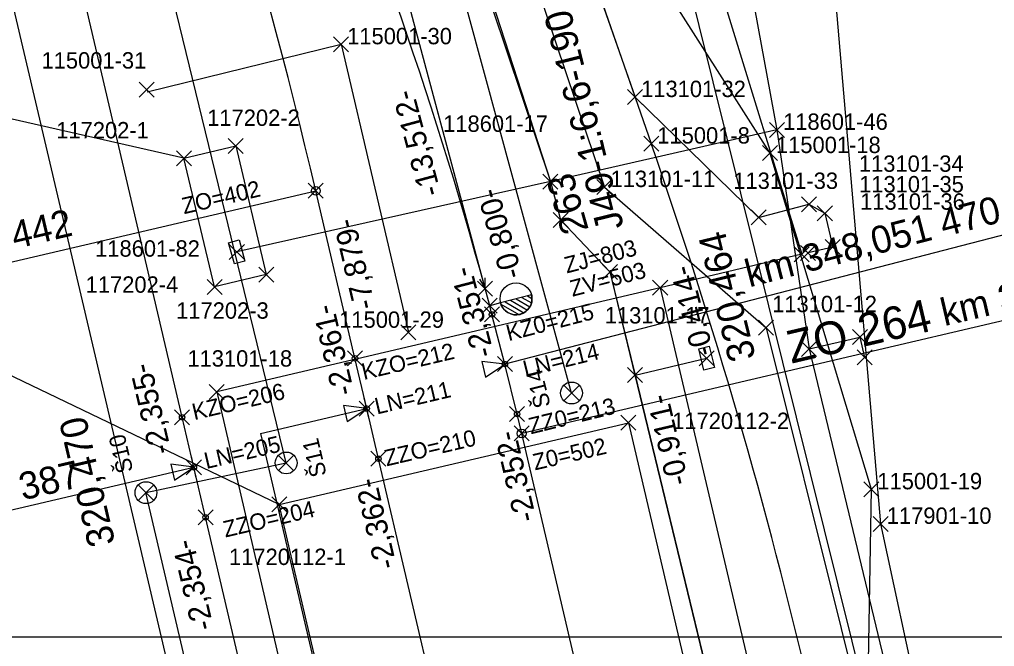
# Model space of a CAD drawing. Extents: x -821029 to -820632, y -1070881 to -1069931.
# Drawn here: x -820817.11 to -820772.47, y -1070448.01 to -1070419.3 of the extents above; entities that cross this region are included whole.
import ezdxf

# ---------------------------------------------------------------- set-up
doc = ezdxf.new("R2010")
doc.units = 0
for name, color, linetype in [('_PS_SO_číslo', 7, 'Continuous'), ('PS-11-02-31', 7, 'Continuous'), ('PS-11-02-41', 7, 'Continuous'), ('PS-11-02-92', 7, 'Continuous'), ('SO-11-10-01', 7, 'Continuous'), ('SO-11-31-01', 7, 'Continuous'), ('SO-11-32-01', 7, 'Continuous'), ('SO-11-50-01', 7, 'Continuous'), ('SO-11-72-0112', 7, 'Continuous'), ('SO-11-72-02', 7, 'Continuous'), ('SO-11-79-01', 7, 'Continuous'), ('SO-11-86-01', 7, 'Continuous'), ('VB_SO-11-10-01', 7, 'Continuous'), ('VB_SO-11-31-01', 7, 'Continuous'), ('VB_SO-11-50-01', 7, 'Continuous'), ('VB_SO-11-72-0112', 7, 'Continuous'), ('VB_SO-11-72-02', 7, 'Continuous'), ('VB_SO-11-79-01', 7, 'Continuous'), ('VB_SO-11-86-01', 7, 'Continuous')]:
    doc.layers.add(name, color=color, linetype=linetype)

msp = doc.modelspace()

# ---------------------------------------------------------------- linework, layer by layer
at = {"layer": '_PS_SO_číslo'}
for p, q in [((-820809.586, -1070425.651), (-820855.128, -1070415.337)), ((-820805.22, -1070441.504), (-820858.235, -1070416.07))]:
    msp.add_line(p, q, dxfattribs=at)
msp.add_lwpolyline([(-820818.962, -1070418.04), (-820767.714, -1070418.04), (-820767.714, -1070447.591), (-820818.962, -1070447.591)], close=True, dxfattribs=at)
at = {"layer": 'PS-11-02-31'}
msp.add_line((-820788.925, -1070435.581), (-820785.655, -1070434.808), dxfattribs=at)
for points in [[(-820959.278, -1070122.218), (-820934.84, -1070144.095), (-820933.002, -1070146.602), (-820925.146, -1070161.738), (-820918.63, -1070175.611), (-820911.367, -1070188.874), (-820902.582, -1070186.65), (-820896.686, -1070196.978), (-820870.459, -1070236.453), (-820846.568, -1070277.079), (-820842.598, -1070282.108), (-820813.472, -1070365.169), (-820809.802, -1070374.33), (-820792.803, -1070426.722), (-820792.342, -1070428.474), (-820790.079, -1070430.856), (-820788.925, -1070435.581), (-820780.392, -1070470.858), (-820770.551, -1070511.609), (-820767.886, -1070524.681), (-820765.297, -1070562.399), (-820759.609, -1070562.181)], [(-820834.739, -1070280.72), (-820830.77, -1070287.401), (-820826.598, -1070295.778), (-820822.74, -1070307.417), (-820822.402, -1070310.542), (-820820.817, -1070316.363), (-820815.079, -1070335.816), (-820806.043, -1070362.212), (-820801.047, -1070374.777), (-820795.979, -1070387.28), (-820794.84, -1070387.997), (-820792.153, -1070393.193), (-820783.482, -1070412.233), (-820783.598, -1070416.458), (-820783.598, -1070418.019), (-820782.431, -1070424.351)], [(-820782.431, -1070424.351), (-820792.803, -1070426.722), (-820807.163, -1070429.943)]]:
    msp.add_lwpolyline(points, dxfattribs=at)
for points in [[(-820807.056, -1070429.395), (-820806.789, -1070430.358), (-820807.271, -1070430.492), (-820807.537, -1070429.528)], [(-820785.529, -1070434.264), (-820785.294, -1070435.236), (-820785.781, -1070435.353), (-820786.015, -1070434.381)]]:
    msp.add_lwpolyline(points, close=True, dxfattribs=at)
at = {"layer": 'PS-11-02-41'}
for points in [[(-820882.988, -1070201.129), (-820875.537, -1070207.75), (-820872.787, -1070212.312), (-820866.572, -1070222.102), (-820863.695, -1070232.226), (-820854.155, -1070247.197), (-820844.785, -1070263.708), (-820834.739, -1070280.72), (-820830.77, -1070287.401), (-820826.598, -1070295.778), (-820822.74, -1070307.417), (-820822.402, -1070310.542), (-820820.817, -1070316.363), (-820815.079, -1070335.816), (-820806.043, -1070362.212), (-820801.047, -1070374.777), (-820795.979, -1070387.28), (-820794.84, -1070387.997), (-820792.153, -1070393.193), (-820783.482, -1070412.233), (-820783.598, -1070416.458), (-820783.598, -1070418.019), (-820782.431, -1070424.351)], [(-820782.431, -1070424.351), (-820792.803, -1070426.722), (-820792.342, -1070428.474), (-820790.079, -1070430.856), (-820770.551, -1070511.609), (-820767.886, -1070524.681), (-820765.297, -1070562.399), (-820758.455, -1070560.768), (-820758.455, -1070561.695), (-820758.455, -1070561.91)]]:
    msp.add_lwpolyline(points, dxfattribs=at)
at = {"layer": 'PS-11-02-92'}
for points in [[(-820882.988, -1070201.129), (-820875.537, -1070207.75), (-820872.787, -1070212.312), (-820866.572, -1070222.102), (-820863.695, -1070232.226), (-820854.155, -1070247.197), (-820844.785, -1070263.708), (-820834.739, -1070280.72), (-820830.77, -1070287.401), (-820826.598, -1070295.778), (-820822.74, -1070307.417), (-820822.402, -1070310.542), (-820820.817, -1070316.363), (-820815.079, -1070335.816), (-820806.043, -1070362.212), (-820801.047, -1070374.777), (-820795.979, -1070387.28), (-820794.84, -1070387.997), (-820792.153, -1070393.193), (-820783.482, -1070412.233), (-820783.598, -1070416.458), (-820783.598, -1070418.019), (-820782.431, -1070424.351)], [(-820782.431, -1070424.351), (-820792.803, -1070426.722), (-820792.342, -1070428.474), (-820790.079, -1070430.856), (-820770.551, -1070511.609), (-820767.886, -1070524.681), (-820765.297, -1070562.399), (-820758.455, -1070560.768), (-820758.455, -1070561.695), (-820758.455, -1070561.91)]]:
    msp.add_lwpolyline(points, dxfattribs=at)
at = {"layer": 'SO-11-10-01'}
for p, q in [((-820795.796, -1070431.621), (-820799.288, -1070418.579)), ((-820761.01, -1070426.297), (-820794.89, -1070435.08)), ((-820832.76, -1070433.979), (-820803.549, -1070427.142)), ((-820764.909, -1070431.414), (-820794.12, -1070438.251)), ((-820795.586, -1070432.404), (-820795.796, -1070431.621)), ((-820793.671, -1070431.908), (-820795.088, -1070432.275)), ((-820793.855, -1070431.954), (-820793.65, -1070432.075)), ((-820795.088, -1070432.275), (-820795.586, -1070432.404)), ((-820795.07, -1070432.327), (-820794.252, -1070432.809)), ((-820794.883, -1070432.22), (-820794.021, -1070432.727)), ((-820794.626, -1070432.154), (-820793.861, -1070432.604)), ((-820794.369, -1070432.087), (-820793.747, -1070432.454)), ((-820794.112, -1070432.021), (-820793.675, -1070432.278)), ((-820794.771, -1070435.566), (-820795.009, -1070434.594)), ((-820801.102, -1070437.6), (-820801.33, -1070436.626)), ((-820806.084, -1070438.254), (-820801.216, -1070437.113)), ((-820806.084, -1070438.254), (-820802.662, -1070452.858)), ((-820809.017, -1070440.29), (-820809.245, -1070439.316)), ((-820828.606, -1070444.357), (-820809.131, -1070439.803)), ((-820811.324, -1070440.966), (-820804.905, -1070439.605))]:
    msp.add_line(p, q, dxfattribs=at)
for points in [[(-820791.836, -1070436.403), (-820804.578, -1070389.555), (-820809.286, -1070391.234), (-820814.195, -1070381.747)], [(-820804.905, -1070439.605), (-820811.403, -1070412.909), (-820819.538, -1070385.143)], [(-820761.019, -1070645.411), (-820786.886, -1070534.867), (-820787.456, -1070532.433), (-820788.025, -1070529.999), (-820808.595, -1070442.095), (-820809.131, -1070439.803), (-820809.668, -1070437.51), (-820820.711, -1070390.317)], [(-820795.586, -1070432.404), (-820799.288, -1070418.579), (-820802.989, -1070404.758)], [(-820790.906, -1070481.165), (-820795.245, -1070462.626), (-820800.677, -1070439.413), (-820801.216, -1070437.113), (-820801.754, -1070434.814), (-820803.549, -1070427.142)], [(-820796.046, -1070431.188), (-820795.796, -1070431.621), (-820795.796, -1070431.121)], [(-820784.431, -1070479.649), (-820794.12, -1070438.251), (-820794.329, -1070437.364), (-820794.89, -1070435.08), (-820795.48, -1070432.804), (-820795.586, -1070432.404)], [(-820795.772, -1070435.683), (-820794.89, -1070435.08), (-820795.951, -1070434.954), (-820795.772, -1070435.683)], [(-820802.104, -1070437.706), (-820801.216, -1070437.113), (-820802.275, -1070436.976), (-820802.104, -1070437.706)], [(-820810.019, -1070440.396), (-820809.131, -1070439.803), (-820810.19, -1070439.666), (-820810.019, -1070440.396)], [(-820717.049, -1070839.458), (-820726.3, -1070799.934), (-820741.684, -1070734.203), (-820752.33, -1070690.998), (-820761.077, -1070655.693), (-820772.47, -1070607.008), (-820783.862, -1070558.323), (-820795.254, -1070509.638), (-820806.647, -1070460.953), (-820811.324, -1070440.966)]]:
    msp.add_lwpolyline(points, dxfattribs=at)
for centre, radius in [((-820803.549, -1070427.142), 0.2), ((-820794.38, -1070432.091), 0.732), ((-820795.48, -1070432.804), 0.125), ((-820801.754, -1070434.814), 0.125), ((-820794.89, -1070435.08), 0.125), ((-820791.836, -1070436.403), 0.5), ((-820801.216, -1070437.113), 0.125), ((-820794.329, -1070437.364), 0.125), ((-820809.668, -1070437.51), 0.125), ((-820794.12, -1070438.251), 0.2), ((-820804.905, -1070439.605), 0.5), ((-820800.677, -1070439.413), 0.125), ((-820809.131, -1070439.803), 0.125), ((-820811.324, -1070440.966), 0.5), ((-820808.595, -1070442.095), 0.125)]:
    msp.add_circle(centre, radius, dxfattribs=at)
msp.add_arc((-820794.38, -1070432.091), 0.732, 194.5518, 14.5127, dxfattribs=at)
for centre, major_axis, ratio, start_param, end_param in [((-821056.703, -1070486.397), (38.305, 257.163), 0.999985, 5.090175, 5.221577), ((-820979.113, -1070481.557), (-128.262, 140.174), 0.999982, 4.237298, 4.383398)]:
    msp.add_ellipse(centre, major_axis=major_axis, ratio=ratio, start_param=start_param, end_param=end_param, dxfattribs=at)
at = {"layer": 'SO-11-31-01'}
for p, q in [((-820786.49, -1070413.14), (-820781.3, -1070430.05)), ((-820781.3, -1070430.05), (-820787.78, -1070431.58)), ((-820787.78, -1070431.58), (-820808.08, -1070436.35)), ((-820808.08, -1070436.35), (-820796.55, -1070485.82))]:
    msp.add_line(p, q, dxfattribs=at)
for points in [[(-820926.07, -1070123.29), (-820916.95, -1070167.12), (-820908.61, -1070171.6), (-820902.99, -1070184.31), (-820895.92, -1070196.33), (-820868.5, -1070237.37), (-820845.66, -1070276.46), (-820841.66, -1070281.51), (-820839.82, -1070285.2), (-820808.13, -1070374.18), (-820790.33, -1070426.97), (-820782.93, -1070433.41), (-820769.19, -1070488.5), (-820779.762, -1070491.365)], [(-820832.57, -1070337.97), (-820821.56, -1070335.44), (-820813.99, -1070356.68), (-820798.47, -1070401.74), (-820795.5, -1070403.96), (-820793.85, -1070408.69), (-820790.57, -1070418.13), (-820788.93, -1070422.85), (-820783.27, -1070428.36), (-820780.97, -1070427.76), (-820780.24, -1070428.17), (-820779.88, -1070429.72), (-820781.01, -1070429.99)], [(-820787.78, -1070431.58), (-820767, -1070520.02), (-820772.54, -1070521.32)]]:
    msp.add_lwpolyline(points, dxfattribs=at)
at = {"layer": 'SO-11-32-01'}
msp.add_lwpolyline([(-820787.62, -1070413.59), (-820787.28, -1070414.46), (-820762.46, -1070514.35), (-820773.88, -1070517.14)], dxfattribs=at)
at = {"layer": 'SO-11-50-01'}
for points in [[(-820831.742, -1070299.721), (-820794.486, -1070406.873), (-820788.19, -1070424.98)], [(-820815.774, -1070338.796), (-820798.172, -1070389.423), (-820789.142, -1070415.392), (-820782.756, -1070425.414), (-820778.113, -1070440.812), (-820778.3, -1070451.359), (-820766.965, -1070499.852)], [(-820811.261, -1070422.612), (-820802.389, -1070420.433), (-820799.304, -1070433.618)]]:
    msp.add_lwpolyline(points, dxfattribs=at)
msp.add_arc((-821024.432, -1070507.111), 250.112, 13.15717, 19.17037, dxfattribs=at)
at = {"layer": 'SO-11-72-0112'}
msp.add_lwpolyline([(-820805.22, -1070441.504), (-820789.231, -1070437.766), (-820778.928, -1070481.843), (-820794.917, -1070485.581)], close=True, dxfattribs=at)
at = {"layer": 'SO-11-72-02'}
msp.add_lwpolyline([(-820809.586, -1070425.651), (-820807.215, -1070425.086), (-820805.812, -1070430.978), (-820808.183, -1070431.543)], close=True, dxfattribs=at)
at = {"layer": 'SO-11-79-01'}
for points in [[(-820832.859, -1070278.435), (-820856.812, -1070291.29), (-820851.463, -1070300.374), (-820846.113, -1070309.459), (-820839.296, -1070322.503), (-820836.663, -1070328.485), (-820822.067, -1070360.696), (-820815.218, -1070377.527), (-820826.198, -1070382.449), (-820824.947, -1070387.213), (-820823.927, -1070391.029), (-820782.064, -1070569.191)], [(-820761.036, -1070511.475), (-820774.105, -1070459.005), (-820777.683, -1070442.395), (-820780.824, -1070405.778), (-820791.175, -1070389.775), (-820795.413, -1070386.908), (-820807.598, -1070359.392), (-820815.489, -1070325.838), (-820825.29, -1070295.054), (-820830.464, -1070283.216), (-820832.859, -1070278.435)]]:
    msp.add_lwpolyline(points, dxfattribs=at)
at = {"layer": 'SO-11-86-01'}
msp.add_line((-820788.925, -1070435.581), (-820785.655, -1070434.808), dxfattribs=at)
for points in [[(-820870.459, -1070236.454), (-820846.568, -1070277.079), (-820842.598, -1070282.108), (-820813.472, -1070365.169), (-820792.803, -1070426.722), (-820792.342, -1070428.474), (-820790.079, -1070430.857), (-820788.924, -1070435.581), (-820780.392, -1070470.858), (-820770.551, -1070511.609), (-820767.886, -1070524.681), (-820765.297, -1070562.4), (-820759.609, -1070562.181), (-820765.131, -1070563.533), (-820782.387, -1070567.755), (-820781.928, -1070569.717), (-820782.387, -1070567.755)], [(-820844.785, -1070263.708), (-820834.739, -1070280.72), (-820830.77, -1070287.401), (-820826.598, -1070295.778), (-820822.74, -1070307.417), (-820822.402, -1070310.542), (-820820.817, -1070316.363), (-820815.079, -1070335.816), (-820806.043, -1070362.212), (-820801.047, -1070374.777), (-820795.979, -1070387.28), (-820794.84, -1070387.997), (-820792.153, -1070393.193), (-820783.482, -1070412.233), (-820783.598, -1070416.458), (-820783.598, -1070418.019), (-820782.431, -1070424.351), (-820780.96, -1070434.384), (-820773.909, -1070463.726), (-820769.347, -1070482.633)], [(-820782.431, -1070424.351), (-820792.803, -1070426.722), (-820807.163, -1070429.943)], [(-820780.96, -1070434.384), (-820778.636, -1070433.841), (-820778.418, -1070434.772)], [(-820780.96, -1070434.384), (-820778.636, -1070433.841), (-820778.418, -1070434.772)]]:
    msp.add_lwpolyline(points, dxfattribs=at)
for points in [[(-820807.056, -1070429.395), (-820806.789, -1070430.358), (-820807.271, -1070430.492), (-820807.537, -1070429.528)], [(-820785.529, -1070434.264), (-820785.294, -1070435.236), (-820785.781, -1070435.353), (-820786.015, -1070434.381)]]:
    msp.add_lwpolyline(points, close=True, dxfattribs=at)
at = {"layer": 'VB_SO-11-10-01'}
for p, q in [((-820803.893, -1070427.486), (-820803.205, -1070426.798)), ((-820803.205, -1070427.486), (-820803.893, -1070426.798)), ((-820796.137, -1070431.975), (-820795.449, -1070431.287)), ((-820795.449, -1070431.975), (-820796.137, -1070431.287)), ((-820795.93, -1070432.748), (-820795.243, -1070432.06)), ((-820795.243, -1070432.748), (-820795.93, -1070432.06)), ((-820795.93, -1070432.748), (-820795.243, -1070432.06)), ((-820795.243, -1070432.748), (-820795.93, -1070432.06)), ((-820795.823, -1070433.148), (-820795.136, -1070432.46)), ((-820795.136, -1070433.148), (-820795.823, -1070432.46)), ((-820802.098, -1070435.158), (-820801.41, -1070434.47)), ((-820801.41, -1070435.158), (-820802.098, -1070434.47)), ((-820795.234, -1070435.424), (-820794.547, -1070434.737)), ((-820794.547, -1070435.424), (-820795.234, -1070434.737)), ((-820792.18, -1070436.747), (-820791.492, -1070436.059)), ((-820791.492, -1070436.747), (-820792.18, -1070436.059)), ((-820801.559, -1070437.457), (-820800.872, -1070436.77)), ((-820800.872, -1070437.457), (-820801.559, -1070436.77)), ((-820810.011, -1070437.853), (-820809.324, -1070437.166)), ((-820809.324, -1070437.853), (-820810.011, -1070437.166)), ((-820794.673, -1070437.708), (-820793.986, -1070437.02)), ((-820793.986, -1070437.708), (-820794.673, -1070437.02)), ((-820794.463, -1070438.595), (-820793.776, -1070437.907)), ((-820793.776, -1070438.595), (-820794.463, -1070437.907)), ((-820801.021, -1070439.757), (-820800.334, -1070439.069)), ((-820800.334, -1070439.757), (-820801.021, -1070439.069)), ((-820809.475, -1070440.146), (-820808.787, -1070439.459)), ((-820808.787, -1070440.146), (-820809.475, -1070439.459)), ((-820805.249, -1070439.949), (-820804.561, -1070439.261)), ((-820804.561, -1070439.949), (-820805.249, -1070439.261)), ((-820811.668, -1070441.31), (-820810.98, -1070440.622)), ((-820810.98, -1070441.31), (-820811.668, -1070440.622)), ((-820808.938, -1070442.439), (-820808.251, -1070441.752)), ((-820808.251, -1070442.439), (-820808.938, -1070441.752))]:
    msp.add_line(p, q, dxfattribs=at)
at = {"layer": 'VB_SO-11-31-01'}
for p, q in [((-820789.274, -1070423.194), (-820788.586, -1070422.506)), ((-820788.586, -1070423.194), (-820789.274, -1070422.506)), ((-820790.674, -1070427.314), (-820789.986, -1070426.626)), ((-820789.986, -1070427.314), (-820790.674, -1070426.626)), ((-820781.314, -1070428.104), (-820780.626, -1070427.416)), ((-820780.626, -1070428.104), (-820781.314, -1070427.416)), ((-820780.584, -1070428.514), (-820779.896, -1070427.826)), ((-820779.896, -1070428.514), (-820780.584, -1070427.826)), ((-820783.614, -1070428.704), (-820782.926, -1070428.016)), ((-820782.926, -1070428.704), (-820783.614, -1070428.016)), ((-820781.644, -1070430.394), (-820780.956, -1070429.706)), ((-820780.956, -1070430.394), (-820781.644, -1070429.706)), ((-820781.354, -1070430.334), (-820780.666, -1070429.646)), ((-820780.666, -1070430.334), (-820781.354, -1070429.646)), ((-820780.224, -1070430.064), (-820779.536, -1070429.376)), ((-820779.536, -1070430.064), (-820780.224, -1070429.376)), ((-820788.124, -1070431.924), (-820787.436, -1070431.236)), ((-820787.436, -1070431.924), (-820788.124, -1070431.236)), ((-820783.274, -1070433.754), (-820782.586, -1070433.066)), ((-820782.586, -1070433.754), (-820783.274, -1070433.066)), ((-820808.424, -1070436.694), (-820807.736, -1070436.006)), ((-820807.736, -1070436.694), (-820808.424, -1070436.006))]:
    msp.add_line(p, q, dxfattribs=at)
at = {"layer": 'VB_SO-11-50-01'}
for p, q in [((-820802.733, -1070420.777), (-820802.045, -1070420.089)), ((-820802.045, -1070420.777), (-820802.733, -1070420.089)), ((-820811.629, -1070422.856), (-820810.941, -1070422.168)), ((-820810.941, -1070422.856), (-820811.629, -1070422.168)), ((-820788.534, -1070425.324), (-820787.846, -1070424.636)), ((-820787.846, -1070425.324), (-820788.534, -1070424.636)), ((-820783.1, -1070425.758), (-820782.412, -1070425.07)), ((-820782.412, -1070425.758), (-820783.1, -1070425.07)), ((-820799.648, -1070433.962), (-820798.96, -1070433.274)), ((-820798.96, -1070433.962), (-820799.648, -1070433.274)), ((-820778.457, -1070441.156), (-820777.769, -1070440.468)), ((-820777.769, -1070441.156), (-820778.457, -1070440.468))]:
    msp.add_line(p, q, dxfattribs=at)
at = {"layer": 'VB_SO-11-72-0112'}
for p, q in [((-820789.575, -1070438.11), (-820788.887, -1070437.422)), ((-820788.887, -1070438.11), (-820789.575, -1070437.422)), ((-820805.564, -1070441.848), (-820804.876, -1070441.16)), ((-820804.876, -1070441.848), (-820805.564, -1070441.16))]:
    msp.add_line(p, q, dxfattribs=at)
at = {"layer": 'VB_SO-11-72-02'}
for p, q in [((-820807.559, -1070425.43), (-820806.871, -1070424.742)), ((-820806.871, -1070425.43), (-820807.559, -1070424.742)), ((-820809.93, -1070425.995), (-820809.242, -1070425.307)), ((-820809.242, -1070425.995), (-820809.93, -1070425.307)), ((-820806.156, -1070431.322), (-820805.468, -1070430.634)), ((-820805.468, -1070431.322), (-820806.156, -1070430.634)), ((-820808.527, -1070431.887), (-820807.839, -1070431.199)), ((-820807.839, -1070431.887), (-820808.527, -1070431.199))]:
    msp.add_line(p, q, dxfattribs=at)
at = {"layer": 'VB_SO-11-79-01'}
for p, q in [((-820778.027, -1070442.739), (-820777.339, -1070442.051)), ((-820777.339, -1070442.739), (-820778.027, -1070442.051))]:
    msp.add_line(p, q, dxfattribs=at)
at = {"layer": 'VB_SO-11-86-01'}
for p, q in [((-820782.775, -1070424.695), (-820782.087, -1070424.007)), ((-820782.087, -1070424.695), (-820782.775, -1070424.007)), ((-820793.147, -1070427.066), (-820792.459, -1070426.378)), ((-820792.459, -1070427.066), (-820793.147, -1070426.378)), ((-820792.686, -1070428.818), (-820791.998, -1070428.13)), ((-820791.998, -1070428.818), (-820792.686, -1070428.13)), ((-820807.507, -1070430.287), (-820806.819, -1070429.599)), ((-820806.819, -1070430.287), (-820807.507, -1070429.599)), ((-820790.423, -1070431.2), (-820789.735, -1070430.512)), ((-820789.735, -1070431.2), (-820790.423, -1070430.512)), ((-820778.98, -1070434.185), (-820778.292, -1070433.497)), ((-820778.292, -1070434.185), (-820778.98, -1070433.497)), ((-820781.304, -1070434.728), (-820780.616, -1070434.04)), ((-820780.616, -1070434.728), (-820781.304, -1070434.04)), ((-820785.999, -1070435.152), (-820785.311, -1070434.464)), ((-820785.311, -1070435.152), (-820785.999, -1070434.464)), ((-820778.762, -1070435.116), (-820778.074, -1070434.428)), ((-820778.074, -1070435.116), (-820778.762, -1070434.428)), ((-820789.269, -1070435.925), (-820788.581, -1070435.237)), ((-820788.581, -1070435.925), (-820789.269, -1070435.237))]:
    msp.add_line(p, q, dxfattribs=at)

# ---------------------------------------------------------------- texts
at = {"layer": 'SO-11-10-01'}
for s, height, rotation, p in [('J49-1:6,6-190', 1.25, 103.7999, (-820789.438, -1070428.785)), ('-13,512-', 1, 104.9907, (-820797.803, -1070427.255)), ('263', 1.25, 105.8266, (-820791.043, -1070428.922)), ('-0,800-', 1, 105.8266, (-820794.068, -1070431.027)), ('km 348,051 470', 1.25, 14.5327, (-820783.701, -1070431.568)), ('km 348,061 442', 1.25, 13.1733, (-820826.285, -1070431.908)), ('-7,879-', 1, 103.1685, (-820800.816, -1070432.464)), ('320,464', 1.25, 103.7999, (-820783.395, -1070434.783)), ('km 348,048 477', 1.25, 13.1727, (-820774.768, -1070433.341)), ('-0,414-', 1, 104.5327, (-820785.309, -1070434.583)), ('-2,351-', 1, 104.5327, (-820795.372, -1070434.642)), ('-2,361-', 1, 103.1685, (-820801.777, -1070436.399)), ('ZO 264 ', 1.5, 13.1727, (-820781.776, -1070435.062)), ('-2,355-', 1, 103.1701, (-820810.152, -1070439.095)), ('-0,911-', 1, 103.1727, (-820786.468, -1070440.512)), ('320,470', 1.25, 103.1806, (-820812.719, -1070443.276)), ('-2,352-', 1, 103.1727, (-820793.439, -1070442.189)), ('km 348,050 387', 1.25, 13.1625, (-820825.926, -1070443.418)), ('-2,362-', 1, 103.1706, (-820799.831, -1070444.351)), ('-2,354-', 1, 103.1705, (-820808.209, -1070447.161))]:
    msp.add_text(s, height=height, rotation=rotation, dxfattribs=at).set_placement(p)
at = {"layer": 'VB_SO-11-10-01'}
for s, rotation, p in [('ZO=402', 13.1685, (-820809.58, -1070428.216)), ('ZJ=803', 14.5327, (-820792.055, -1070430.929)), ('ZV=503', 14.5327, (-820791.799, -1070431.997)), ('KZ0=215', 14.5327, (-820794.721, -1070434.032)), ('KZO=212', 13.171, (-820801.351, -1070435.807)), ('LN=214', 13.7999, (-820793.954, -1070435.68)), ('Š14', 103.7999, (-820792.789, -1070436.986)), ('KZO=206', 13.1705, (-820809.112, -1070437.648)), ('LN=211', 13.1891, (-820800.75, -1070437.387)), ('ZZ0=213', 13.7999, (-820793.698, -1070438.296)), ('ZZO=210', 13.1706, (-820800.305, -1070439.763)), ('Š10', 103.1806, (-820811.903, -1070439.972)), ('LN=205', 13.1705, (-820808.559, -1070439.885)), ('Š11', 103.1625, (-820803.045, -1070440.154)), ('Z0=502', 13.1727, (-820793.515, -1070439.949)), ('ZZO=204', 13.1705, (-820807.69, -1070443.023))]:
    msp.add_text(s, height=0.75, rotation=rotation, dxfattribs=at).set_placement(p)
at = {"layer": 'VB_SO-11-31-01'}
for s, p in [(' 113101-32', (-820788.93, -1070422.85)), (' 113101-34', (-820778.96, -1070426.273)), (' 113101-11', (-820790.33, -1070426.97)), (' 113101-33', (-820784.71, -1070427.056)), (' 113101-35', (-820778.95, -1070427.215)), (' 113101-36', (-820778.904, -1070428.008)), (' 113101-12', (-820782.93, -1070432.701)), (' 113101-17', (-820790.596, -1070433.219)), (' 113101-18', (-820809.704, -1070435.194))]:
    msp.add_text(s, height=0.75, dxfattribs=at).set_placement(p)
at = {"layer": 'VB_SO-11-50-01'}
for s, p in [(' 115001-30', (-820802.389, -1070420.433)), (' 115001-31', (-820816.384, -1070421.545)), (' 115001-8', (-820788.19, -1070424.98)), (' 115001-18', (-820782.756, -1070425.414)), (' 115001-29', (-820802.754, -1070433.416)), (' 115001-19', (-820778.113, -1070440.812))]:
    msp.add_text(s, height=0.75, dxfattribs=at).set_placement(p)
at = {"layer": 'VB_SO-11-72-0112'}
for s, p in [(' 11720112-2', (-820787.508, -1070438.051)), (' 11720112-1', (-820807.799, -1070444.279))]:
    msp.add_text(s, height=0.75, dxfattribs=at).set_placement(p)
at = {"layer": 'VB_SO-11-72-02'}
for s, p in [(' 117202-2', (-820808.798, -1070424.172)), (' 117202-1', (-820815.711, -1070424.742)), (' 117202-4', (-820814.363, -1070431.811)), (' 117202-3', (-820810.22, -1070433))]:
    msp.add_text(s, height=0.75, dxfattribs=at).set_placement(p)
at = {"layer": 'VB_SO-11-79-01'}
msp.add_text(' 117901-10', height=0.75, dxfattribs=at).set_placement((-820777.683, -1070442.395))
at = {"layer": 'VB_SO-11-86-01'}
for s, p in [(' 118601-17', (-820797.995, -1070424.443)), (' 118601-46', (-820782.431, -1070424.351)), (' 118601-82', (-820813.929, -1070430.159))]:
    msp.add_text(s, height=0.75, dxfattribs=at).set_placement(p)

doc.saveas('drawing.dxf')
